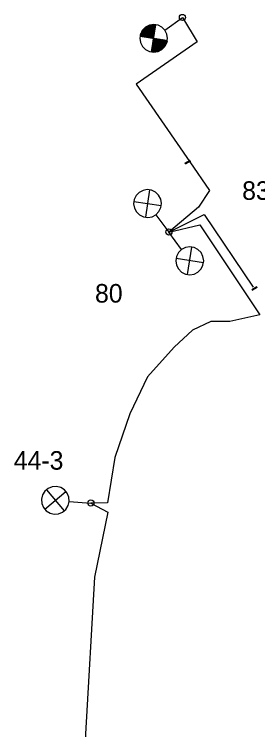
# Model space of a CAD drawing. Extents: x 25497851 to 25498523, y 6686544 to 6687372.
# Drawn here: x 25498258.4 to 25498297.7, y 6687256.4 to 6687372 of the extents above; entities that cross this region are included whole.
import ezdxf

# ---------------------------------------------------------------- set-up
doc = ezdxf.new("R2010")
doc.units = 0
for name, color, linetype in [('EL_CABLE_MAA', 7, 'Continuous'), ('KEYGWT_ANNOTATION', 7, 'Continuous'), ('Taso 1', 7, 'Continuous'), ('Taso 50', 7, 'Continuous')]:
    doc.layers.add(name, color=color, linetype=linetype)

msp = doc.modelspace()

# ---------------------------------------------------------------- linework, layer by layer
at = {"layer": 'EL_CABLE_MAA'}
for points in [[(25498285.58, 6687371.52), (25498287.96, 6687367.55), (25498278.11, 6687360.76), (25498286.76, 6687348.18)], [(25498286.76, 6687348.18), (25498289.94, 6687343.56), (25498288.15, 6687340.87), (25498283.39, 6687336.84)], [(25498283.39, 6687336.84), (25498289.08, 6687339.68), (25498297.01, 6687327.93)], [(25498283.39, 6687336.84), (25498288.4, 6687337.99), (25498298.11, 6687323.46), (25498293.24, 6687322.37), (25498290.14, 6687322.41), (25498287.2, 6687321), (25498284.25, 6687318.23), (25498279.91, 6687313.45), (25498277.1, 6687307.48), (25498274.67, 6687300.43), (25498273.49, 6687293.07), (25498270.78, 6687293.04)], [(25498270.78, 6687293.04), (25498273.51, 6687291.57), (25498271.36, 6687281.07), (25498269.91, 6687255.77), (25498269.86, 6687254.08), (25498266.81, 6687251.14)]]:
    msp.add_lwpolyline(points, dxfattribs=at)
at = {"layer": 'Taso 1'}
for p, q in [((25498282.75, 6687369.47), (25498285.58, 6687371.52)), ((25498280.58, 6687365.95), (25498281.28, 6687370.34)), ((25498278.74, 6687368.49), (25498283.13, 6687367.8)), ((25498285.99, 6687347.99), (25498286.84, 6687348.47)), ((25498286.06, 6687347.87), (25498286.91, 6687348.35)), ((25498280.25, 6687343.64), (25498279.62, 6687339.24)), ((25498277.73, 6687341.75), (25498282.13, 6687341.13)), ((25498281.28, 6687339.64), (25498283.39, 6687336.84)), ((25498285.44, 6687334.01), (25498283.39, 6687336.84)), ((25498286.42, 6687329.99), (25498287.11, 6687334.38)), ((25498288.96, 6687331.84), (25498284.57, 6687332.54)), ((25498296.78, 6687327.55), (25498297.62, 6687328.04)), ((25498296.85, 6687327.43), (25498297.69, 6687327.92)), ((25498263.35, 6687292.05), (25498266.73, 6687294.93)), ((25498263.6, 6687295.18), (25498266.49, 6687291.8)), ((25498267.29, 6687293.31), (25498270.78, 6687293.04))]:
    msp.add_line(p, q, dxfattribs=at)
for points in [[(25498279.11, 6687366.82), (25498279.61, 6687366.33), (25498280.24, 6687366.01), (25498280.93, 6687365.9), (25498281.63, 6687366.01), (25498282.25, 6687366.32), (25498282.75, 6687366.82), (25498283.07, 6687367.45), (25498283.18, 6687368.14), (25498283.07, 6687368.84), (25498282.75, 6687369.47), (25498282.25, 6687369.96), (25498281.63, 6687370.28), (25498280.93, 6687370.39), (25498280.24, 6687370.28), (25498279.61, 6687369.97), (25498279.11, 6687369.47), (25498278.79, 6687368.84), (25498278.68, 6687368.15), (25498278.79, 6687367.45)], [(25498278.58, 6687343.24), (25498278.09, 6687342.73), (25498277.78, 6687342.1), (25498277.68, 6687341.4), (25498277.81, 6687340.71), (25498278.13, 6687340.09), (25498278.64, 6687339.6), (25498279.27, 6687339.29), (25498279.97, 6687339.19), (25498280.66, 6687339.31), (25498281.28, 6687339.64), (25498281.77, 6687340.14), (25498282.08, 6687340.78), (25498282.18, 6687341.47), (25498282.06, 6687342.17), (25498281.73, 6687342.79), (25498281.23, 6687343.28), (25498280.6, 6687343.59), (25498279.9, 6687343.69), (25498279.21, 6687343.57)], [(25498288.09, 6687330.37), (25498288.58, 6687330.87), (25498288.9, 6687331.49), (25498289.01, 6687332.19), (25498288.9, 6687332.88), (25498288.59, 6687333.51), (25498288.09, 6687334.01), (25498287.46, 6687334.33), (25498286.77, 6687334.44), (25498286.07, 6687334.33), (25498285.44, 6687334.01), (25498284.95, 6687333.51), (25498284.63, 6687332.88), (25498284.52, 6687332.19), (25498284.63, 6687331.49), (25498284.94, 6687330.87), (25498285.44, 6687330.37), (25498286.07, 6687330.05), (25498286.76, 6687329.94), (25498287.46, 6687330.05)], [(25498262.8, 6687293.67), (25498262.86, 6687292.97), (25498263.13, 6687292.31), (25498263.58, 6687291.78), (25498264.18, 6687291.41), (25498264.87, 6687291.25), (25498265.57, 6687291.3), (25498266.22, 6687291.57), (25498266.75, 6687292.03), (25498267.12, 6687292.63), (25498267.29, 6687293.31), (25498267.23, 6687294.02), (25498266.96, 6687294.67), (25498266.51, 6687295.2), (25498265.91, 6687295.57), (25498265.22, 6687295.73), (25498264.52, 6687295.68), (25498263.87, 6687295.41), (25498263.33, 6687294.95), (25498262.97, 6687294.35)]]:
    msp.add_lwpolyline(points, close=True, dxfattribs=at)
for centre in [(25498285.58, 6687371.52), (25498283.39, 6687336.84), (25498270.78, 6687293.04)]:
    msp.add_circle(centre, 0.5, dxfattribs=at)
at = {"layer": 'Taso 50'}
for p, q in [((25498280.98, 6687368.42), (25498279.8, 6687370.04)), ((25498280.99, 6687368.49), (25498279.84, 6687370.07)), ((25498281, 6687368.56), (25498279.88, 6687370.1)), ((25498281.01, 6687368.63), (25498279.92, 6687370.13)), ((25498281.02, 6687368.7), (25498279.99, 6687370.12)), ((25498281.03, 6687368.77), (25498280.03, 6687370.15)), ((25498281.04, 6687368.84), (25498280.07, 6687370.18)), ((25498281.05, 6687368.91), (25498280.11, 6687370.21)), ((25498281.06, 6687368.98), (25498280.15, 6687370.24)), ((25498281.08, 6687369.05), (25498280.19, 6687370.27)), ((25498281.09, 6687369.12), (25498280.24, 6687370.28)), ((25498281.1, 6687369.19), (25498280.3, 6687370.28)), ((25498281.11, 6687369.26), (25498280.37, 6687370.27)), ((25498281.12, 6687369.33), (25498280.41, 6687370.3)), ((25498281.13, 6687369.4), (25498280.48, 6687370.29)), ((25498281.14, 6687369.47), (25498280.52, 6687370.32)), ((25498281.15, 6687369.54), (25498280.58, 6687370.33)), ((25498281.16, 6687369.61), (25498280.63, 6687370.34)), ((25498281.17, 6687369.68), (25498280.7, 6687370.33)), ((25498281.19, 6687369.75), (25498280.74, 6687370.36)), ((25498281.2, 6687369.82), (25498280.81, 6687370.35)), ((25498281.21, 6687369.89), (25498280.86, 6687370.38)), ((25498281.22, 6687369.96), (25498280.92, 6687370.36)), ((25498281.23, 6687370.03), (25498280.97, 6687370.39)), ((25498281.24, 6687370.1), (25498281.04, 6687370.38)), ((25498281.25, 6687370.17), (25498281.11, 6687370.37)), ((25498281.26, 6687370.24), (25498281.17, 6687370.36)), ((25498279.12, 6687368.43), (25498278.79, 6687368.88)), ((25498279.19, 6687368.42), (25498278.83, 6687368.91)), ((25498279.26, 6687368.41), (25498278.87, 6687368.94)), ((25498279.32, 6687368.4), (25498278.88, 6687369.01)), ((25498279.39, 6687368.39), (25498278.92, 6687369.04)), ((25498279.46, 6687368.38), (25498278.94, 6687369.1)), ((25498279.53, 6687368.37), (25498278.98, 6687369.13)), ((25498279.6, 6687368.35), (25498278.99, 6687369.2)), ((25498279.67, 6687368.34), (25498279.03, 6687369.23)), ((25498279.74, 6687368.33), (25498279.04, 6687369.3)), ((25498279.81, 6687368.32), (25498279.08, 6687369.33)), ((25498279.88, 6687368.31), (25498279.09, 6687369.4)), ((25498279.95, 6687368.3), (25498279.11, 6687369.47)), ((25498280.02, 6687368.29), (25498279.14, 6687369.5)), ((25498280.09, 6687368.28), (25498279.18, 6687369.53)), ((25498280.16, 6687368.27), (25498279.22, 6687369.56)), ((25498280.23, 6687368.26), (25498279.26, 6687369.59)), ((25498280.3, 6687368.24), (25498279.3, 6687369.62)), ((25498280.37, 6687368.23), (25498279.34, 6687369.65)), ((25498280.44, 6687368.22), (25498279.36, 6687369.72)), ((25498280.51, 6687368.21), (25498279.4, 6687369.75)), ((25498280.58, 6687368.2), (25498279.44, 6687369.78)), ((25498280.65, 6687368.19), (25498279.48, 6687369.81)), ((25498280.72, 6687368.18), (25498279.52, 6687369.84)), ((25498280.79, 6687368.17), (25498279.56, 6687369.87)), ((25498280.86, 6687368.16), (25498279.57, 6687369.94)), ((25498280.93, 6687368.14), (25498279.61, 6687369.97)), ((25498280.94, 6687368.21), (25498279.65, 6687369.99)), ((25498280.95, 6687368.28), (25498279.72, 6687369.98)), ((25498280.96, 6687368.35), (25498279.76, 6687370.01)), ((25498278.84, 6687368.48), (25498278.75, 6687368.6)), ((25498278.91, 6687368.47), (25498278.76, 6687368.67)), ((25498278.98, 6687368.45), (25498278.8, 6687368.7)), ((25498279.05, 6687368.44), (25498278.81, 6687368.77)), ((25498280.68, 6687367.72), (25498280.68, 6687367.72)), ((25498280.86, 6687367.73), (25498281.98, 6687366.19)), ((25498282.06, 6687366.25), (25498280.89, 6687367.87)), ((25498282.1, 6687366.28), (25498280.9, 6687367.94)), ((25498282.14, 6687366.31), (25498280.91, 6687368)), ((25498282.02, 6687366.22), (25498280.91, 6687367.75)), ((25498282.21, 6687366.29), (25498280.92, 6687368.07)), ((25498282.25, 6687366.32), (25498280.93, 6687368.15)), ((25498282.29, 6687366.35), (25498281, 6687368.13)), ((25498281.07, 6687368.12), (25498282.31, 6687366.42)), ((25498281.14, 6687368.11), (25498282.35, 6687366.45)), ((25498281.21, 6687368.1), (25498282.39, 6687366.48)), ((25498281.28, 6687368.09), (25498282.43, 6687366.51)), ((25498281.35, 6687368.08), (25498282.47, 6687366.54)), ((25498281.42, 6687368.07), (25498282.5, 6687366.57)), ((25498281.49, 6687368.06), (25498282.52, 6687366.64)), ((25498281.56, 6687368.05), (25498282.56, 6687366.67)), ((25498281.63, 6687368.03), (25498282.6, 6687366.7)), ((25498281.7, 6687368.02), (25498282.64, 6687366.73)), ((25498281.77, 6687368.01), (25498282.65, 6687366.8)), ((25498281.84, 6687368), (25498282.69, 6687366.83)), ((25498281.91, 6687367.99), (25498282.73, 6687366.86)), ((25498281.98, 6687367.98), (25498282.77, 6687366.89)), ((25498282.05, 6687367.97), (25498282.78, 6687366.96)), ((25498282.12, 6687367.96), (25498282.82, 6687366.99)), ((25498282.19, 6687367.95), (25498282.83, 6687367.06)), ((25498282.26, 6687367.93), (25498282.88, 6687367.08)), ((25498282.33, 6687367.92), (25498282.89, 6687367.15)), ((25498282.4, 6687367.91), (25498282.93, 6687367.18)), ((25498282.47, 6687367.9), (25498282.94, 6687367.25)), ((25498282.54, 6687367.89), (25498282.98, 6687367.28)), ((25498282.61, 6687367.88), (25498282.99, 6687367.35)), ((25498282.68, 6687367.87), (25498283.03, 6687367.38)), ((25498282.75, 6687367.86), (25498283.04, 6687367.45)), ((25498282.82, 6687367.85), (25498283.05, 6687367.52)), ((25498282.89, 6687367.83), (25498283.09, 6687367.55)), ((25498282.96, 6687367.82), (25498283.1, 6687367.62)), ((25498283.03, 6687367.81), (25498283.11, 6687367.69)), ((25498280.69, 6687366.61), (25498281.16, 6687365.96)), ((25498280.7, 6687366.68), (25498281.23, 6687365.95)), ((25498280.71, 6687366.75), (25498281.27, 6687365.98)), ((25498280.72, 6687366.82), (25498281.34, 6687365.97)), ((25498280.73, 6687366.89), (25498281.38, 6687366)), ((25498280.74, 6687366.96), (25498281.45, 6687365.99)), ((25498280.75, 6687367.03), (25498281.49, 6687366.02)), ((25498280.77, 6687367.1), (25498281.56, 6687366)), ((25498280.78, 6687367.17), (25498281.6, 6687366.03)), ((25498280.79, 6687367.24), (25498281.67, 6687366.02)), ((25498281.71, 6687366.05), (25498280.8, 6687367.31)), ((25498281.75, 6687366.08), (25498280.81, 6687367.38)), ((25498281.79, 6687366.11), (25498280.82, 6687367.45)), ((25498281.83, 6687366.14), (25498280.83, 6687367.52)), ((25498280.84, 6687367.59), (25498281.87, 6687366.17)), ((25498281.94, 6687366.17), (25498280.86, 6687367.66)), ((25498280.6, 6687366.05), (25498280.66, 6687365.97)), ((25498280.61, 6687366.12), (25498280.76, 6687365.92)), ((25498280.62, 6687366.19), (25498280.83, 6687365.91)), ((25498280.63, 6687366.26), (25498280.87, 6687365.94)), ((25498280.64, 6687366.33), (25498280.94, 6687365.92)), ((25498280.65, 6687366.4), (25498281.01, 6687365.91)), ((25498280.67, 6687366.47), (25498281.05, 6687365.94)), ((25498280.68, 6687366.54), (25498281.12, 6687365.93))]:
    msp.add_line(p, q, dxfattribs=at)

# ---------------------------------------------------------------- texts
at = {"layer": 'KEYGWT_ANNOTATION'}
for s, p in [('83', (25498295.23, 6687342.04)), ('80', (25498271.45, 6687325.44)), ('44-3', (25498258.32, 6687298.44))]:
    msp.add_text(s, height=3, dxfattribs=at).set_placement(p)

doc.saveas('drawing.dxf')
